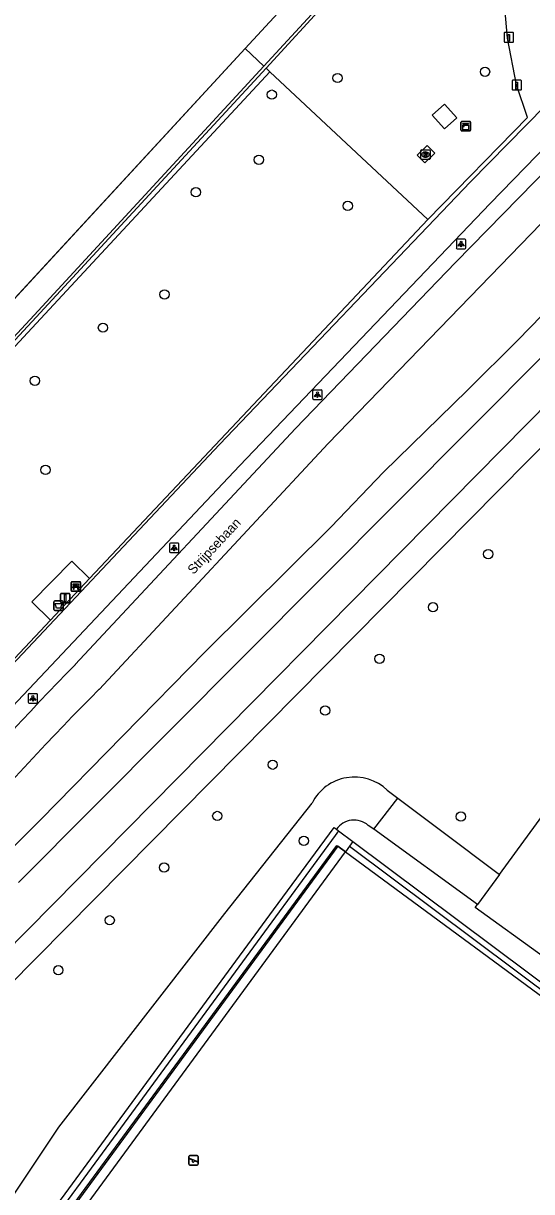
# Model space of a CAD drawing. Extents: x 155640 to 156810, y 382822 to 384046.
# Drawn here: x 156314.7 to 156368.2, y 383202.9 to 383326 of the extents above; entities that cross this region are included whole.
import ezdxf

# ---------------------------------------------------------------- set-up
doc = ezdxf.new("R2010")
doc.units = 0
for name, color, linetype in [('IMGEO_Afvalbak', 7, 'Continuous'), ('IMGEO_Bank', 7, 'Continuous'), ('IMGEO_Berm_groen', 7, 'Continuous'), ('IMGEO_Boom', 7, 'Continuous'), ('IMGEO_Fietspad_gesloten', 7, 'Continuous'), ('IMGEO_Groenvoorziening', 7, 'Continuous'), ('IMGEO_Haag', 7, 'Continuous'), ('IMGEO_Hek', 7, 'Continuous'), ('IMGEO_Kast', 7, 'Continuous'), ('IMGEO_Lichtpunt', 7, 'Continuous'), ('IMGEO_Openbare_ruimte_label', 7, 'Continuous'), ('IMGEO_Paal', 7, 'Continuous'), ('IMGEO_Pand', 7, 'Continuous'), ('IMGEO_Rioolput', 7, 'Continuous'), ('IMGEO_Speelvoorziening', 7, 'Continuous'), ('IMGEO_Verkeersbordpaal', 7, 'Continuous'), ('IMGEO_Voetpad_gesloten', 7, 'Continuous'), ('IMGEO_Voetpad_open', 7, 'Continuous'), ('IMGEO_Waterloop', 7, 'Continuous')]:
    doc.layers.add(name, color=color, linetype=linetype)

msp = doc.modelspace()

# ---------------------------------------------------------------- linework, layer by layer
at = {"layer": 'IMGEO_Afvalbak'}
for p, q in [((156317.87, 383264.25), (156317.87, 383265.05)), ((156317.87, 383265.05), (156317.87, 383264.25)), ((156317.97, 383265.15), (156318.76, 383265.15)), ((156318.76, 383265.15), (156317.97, 383265.15)), ((156318.86, 383265.05), (156318.86, 383264.25)), ((156318.86, 383264.25), (156318.86, 383265.05)), ((156318.76, 383264.15), (156317.97, 383264.15)), ((156317.97, 383264.15), (156318.76, 383264.15))]:
    msp.add_line(p, q, dxfattribs=at)
msp.add_lwpolyline([(156318.02, 383264.86), (156318.72, 383264.86), (156318.57, 383264.39), (156318.17, 383264.39), (156318.02, 383264.86)], dxfattribs=at)
for centre, start, end in [((156317.97, 383265.05), 90, 180), ((156317.97, 383265.05), 90, 180), ((156318.76, 383265.05), 0, 90), ((156318.76, 383265.05), 360, 90), ((156317.97, 383264.25), 180, 270), ((156317.97, 383264.25), 180, 270), ((156318.76, 383264.25), 270, 0), ((156318.76, 383264.25), 270, 0)]:
    msp.add_arc(centre, 0.1, start, end, dxfattribs=at)
at = {"layer": 'IMGEO_Bank'}
for p, q in [((156319.7, 383266.23), (156319.7, 383267.07)), ((156319.7, 383267.07), (156319.7, 383266.23)), ((156319.77, 383267.16), (156320.62, 383267.16)), ((156320.62, 383267.16), (156319.77, 383267.16)), ((156320.7, 383267.08), (156320.7, 383266.24)), ((156320.7, 383266.24), (156320.7, 383267.08)), ((156320.63, 383266.16), (156319.78, 383266.16)), ((156319.78, 383266.16), (156320.63, 383266.16)), ((156320.4, 383266.55), (156320, 383266.55)), ((156320.01, 383266.66), (156320.01, 383266.77)), ((156320.05, 383266.77), (156320.05, 383266.66)), ((156320.34, 383266.77), (156320.06, 383266.77)), ((156320.06, 383266.66), (156320.34, 383266.66)), ((156320.35, 383266.66), (156320.35, 383266.77)), ((156320.39, 383266.77), (156320.39, 383266.66))]:
    msp.add_line(p, q, dxfattribs=at)
for points in [[(156319.95, 383266.55), (156319.8, 383266.55), (156319.92, 383266.66), (156320, 383266.66)], [(156320, 383266.77), (156319.92, 383266.77), (156319.92, 383266.94), (156320.48, 383266.94), (156320.48, 383266.77), (156320.4, 383266.77)], [(156320, 383266.55), (156320, 383266.34), (156319.95, 383266.34), (156319.95, 383266.55)], [(156320.4, 383266.66), (156320.48, 383266.66), (156320.59, 383266.55), (156320.45, 383266.55)], [(156320.45, 383266.55), (156320.45, 383266.34), (156320.4, 383266.34), (156320.4, 383266.55)]]:
    msp.add_lwpolyline(points, dxfattribs=at)
for centre, radius, start, end in [((156319.78, 383267.08), 0.0779, 92.4484, 184.2845), ((156319.78, 383267.08), 0.0779, 92.4484, 184.2845), ((156320.62, 383267.08), 0.0779, 2.4484, 94.2845), ((156320.62, 383267.08), 0.0779, 2.4484, 94.2845), ((156319.78, 383266.24), 0.0779, 182.4484, 274.2845), ((156319.78, 383266.24), 0.0779, 182.4484, 274.2845), ((156319.95, 383266.55), 0.00671, 2.8957, 87.1043), ((156320, 383266.77), 0.00671, 2.8957, 87.1043), ((156320, 383266.66), 0.00671, 272.8957, 357.1043), ((156320, 383266.55), 0.00671, 92.8957, 177.1043), ((156320.06, 383266.77), 0.00671, 92.8957, 177.1043), ((156320.06, 383266.66), 0.00671, 182.8957, 267.1043), ((156320.34, 383266.77), 0.00671, 2.8957, 87.1043), ((156320.34, 383266.66), 0.00671, 272.8957, 357.1043), ((156320.4, 383266.77), 0.00671, 92.8957, 177.1043), ((156320.4, 383266.66), 0.00671, 182.8957, 267.1043), ((156320.4, 383266.55), 0.00671, 2.8957, 87.1043), ((156320.45, 383266.55), 0.00671, 92.8957, 177.1043), ((156320.62, 383266.24), 0.0779, 272.4484, 4.2845), ((156320.62, 383266.24), 0.0779, 272.4484, 4.2845)]:
    msp.add_arc(centre, radius, start, end, dxfattribs=at)
at = {"layer": 'IMGEO_Berm_groen'}
msp.add_lwpolyline([(156233.03, 383113.17), (156252.87, 383146.34), (156268.6, 383172.65), (156299.81, 383224.82), (156307.16, 383232.79), (156316.47, 383242.07), (156333.8, 383259.79), (156347.07, 383272.96), (156352.59, 383278.7), (156361.43, 383287.34), (156366.72, 383292.6), (156371.83, 383297.85), (156374.75, 383300.78), (156375.78, 383301.56), (156376.76, 383302.04), (156377.67, 383302.26), (156378.4, 383302.19), (156379.25, 383300.96), (156381.37, 383298.41), (156381.9, 383296.9), (156381.82, 383296.44)], dxfattribs=at)
at = {"layer": 'IMGEO_Boom'}
for centre in [(156363.28, 383320.89), (156347.75, 383320.23), (156340.83, 383318.48), (156339.47, 383311.62), (156332.84, 383308.2), (156348.83, 383306.76), (156329.53, 383297.43), (156323.05, 383293.93), (156315.88, 383288.34), (156317, 383278.95), (156363.62, 383270.08), (156357.8, 383264.48), (156352.17, 383259.05), (156346.45, 383253.59), (156340.92, 383247.89), (156335.09, 383242.49), (156360.74, 383242.43), (156344.2, 383239.87), (156329.49, 383237.06), (156323.76, 383231.5), (156318.35, 383226.24)]:
    msp.add_circle(centre, 0.489, dxfattribs=at)
at = {"layer": 'IMGEO_Fietspad_gesloten'}
for points in [[(156380.19, 383321.22), (156360.18, 383300.8), (156343.33, 383283.31), (156320.14, 383258.45)], [(156373.43, 383309.29), (156346.78, 383281.73), (156322.64, 383255.83)]]:
    msp.add_lwpolyline(points, dxfattribs=at)
for centre, radius, start, end in [((156587.61, 382998.36), 373.08, 135.8003, 142.4789), ((156555.25, 383025.41), 327.42, 135.271, 142.7864)]:
    msp.add_arc(centre, radius, start, end, dxfattribs=at)
at = {"layer": 'IMGEO_Groenvoorziening'}
for points in [[(156357.25, 383305.32), (156367.75, 383316.07), (156366.58, 383319.5), (156365.66, 383324.43), (156365.29, 383328.46), (156365.54, 383332.04), (156366.67, 383336.3), (156360.1, 383342.13), (156329.37, 383369.36), (156313.77, 383385.4), (156306.65, 383393.61), (156299.36, 383400.93)], [(156288.95, 383393.96), (156316.64, 383368.45), (156350.49, 383336.86), (156338.02, 383323.34)], [(156338.02, 383323.34), (156309.57, 383292.51)], [(156338.02, 383323.34), (156340, 383321.48)], [(156340.22, 383321.28), (156340.63, 383320.89)], [(156340.63, 383320.89), (156263.23, 383237.5), (156269.6, 383231.1), (156281.37, 383219.26), (156285.68, 383225.7), (156290.18, 383232.04), (156294.91, 383238.21), (156299.88, 383244.1), (156305.05, 383249.89), (156317.51, 383263.11)], [(156340.63, 383320.89), (156357.25, 383305.32)], [(156321.64, 383267.49), (156357.25, 383305.32)], [(156381.82, 383296.44), (156381.71, 383295.88), (156381.07, 383294.35), (156380.04, 383292.49), (156379.11, 383291.06), (156378.01, 383290.13), (156376.6, 383288.82), (156373.81, 383286.02), (156313.07, 383224.54), (156307.2, 383217.74), (156241.78, 383106.75)], [(156348.59, 383238.71), (156375.36, 383218.99), (156378.41, 383223.14), (156420.05, 383279.86), (156508.01, 383215.28), (156463.33, 383154.47)], [(156364.79, 383236.34), (156370.31, 383243.89), (156369.57, 383244.47), (156383.71, 383263.94), (156385.33, 383262.76), (156387.53, 383265.66), (156391.32, 383262.89), (156389.23, 383259.91), (156390.72, 383258.76), (156401.82, 383273.86)], [(156352.99, 383245.2), (156354.1, 383244.36)], [(156274.52, 383137.65), (156272.97, 383139.84), (156287.11, 383161.71), (156301.3, 383184.1), (156318.42, 383209.69), (156335.89, 383232.22), (156345.08, 383243.85)], [(156351.56, 383241.09), (156354.1, 383244.36)], [(156354.1, 383244.36), (156358.6, 383240.99), (156364.79, 383236.34)], [(156351.56, 383241.09), (156350.99, 383241.5)], [(156347.86, 383240.92), (156349.37, 383239.8)], [(156362.47, 383233.16), (156351.56, 383241.09)], [(156263.21, 383119.65), (156264.36, 383121.23), (156288.72, 383154.97), (156291.74, 383159.18), (156306.4, 383179.59), (156304.62, 383180.71), (156347.66, 383239.39), (156347.78, 383239.3)], [(156349.01, 383239.31), (156348.59, 383238.71)], [(156364.79, 383236.34), (156362.47, 383233.16)], [(156369.65, 383227.96), (156369.42, 383227.64), (156362.25, 383232.86), (156362.47, 383233.16)]]:
    msp.add_lwpolyline(points, dxfattribs=at)
for centre, radius, start, end in [((156349.53, 383241.59), 5, 46.2363, 153.0781), ((156349.49, 383239.78), 2.28, 48.9249, 144.7835)]:
    msp.add_arc(centre, radius, start, end, dxfattribs=at)
at = {"layer": 'IMGEO_Haag'}
for points in [[(156346.65, 383328.74), (156340, 383321.48)], [(156340.22, 383321.28), (156346.88, 383328.53), (156346.65, 383328.74)], [(156340, 383321.48), (156315.81, 383295.23), (156259.53, 383234.53), (156235.77, 383256.44), (156228.39, 383263.35)], [(156259.55, 383234.11), (156316.03, 383295.02), (156340.22, 383321.28)], [(156274.52, 383137.65), (156304.64, 383179.46), (156302.9, 383180.65), (156341.02, 383232.61), (156347.38, 383241.29), (156347.63, 383241.1)], [(156347.86, 383240.92), (156347.5, 383240.44), (156303.8, 383180.86), (156305.52, 383179.66), (156262.61, 383120.09)], [(156347.63, 383241.1), (156347.86, 383240.92)], [(156349.37, 383239.8), (156349.01, 383239.31)], [(156349.01, 383239.31), (156375.35, 383219.61), (156376.03, 383220.55)], [(156349.37, 383239.8), (156375.22, 383220.46), (156375.57, 383220.93)]]:
    msp.add_lwpolyline(points, dxfattribs=at)
at = {"layer": 'IMGEO_Hek'}
for points in [[(156284.23, 383388.92), (156288.95, 383393.96), (156316.64, 383368.45), (156350.49, 383336.86), (156338.02, 383323.34)], [(156338.02, 383323.34), (156309.48, 383292.4)], [(156340.63, 383320.89), (156263.23, 383237.5), (156269.6, 383231.1)], [(156357.25, 383305.32), (156340.63, 383320.89)], [(156281.37, 383219.26), (156285.68, 383225.7), (156290.18, 383232.04), (156294.91, 383238.21), (156299.88, 383244.1), (156305.05, 383249.89), (156317.51, 383263.11), (156321.64, 383267.49), (156357.25, 383305.32)], [(156291.74, 383159.18), (156306.4, 383179.59), (156304.62, 383180.71), (156347.66, 383239.39), (156347.78, 383239.3)], [(156348.59, 383238.71), (156347.78, 383239.3)], [(156348.59, 383238.71), (156375.36, 383218.99), (156378.41, 383223.14)]]:
    msp.add_lwpolyline(points, dxfattribs=at)
at = {"layer": 'IMGEO_Kast'}
for p, q in [((156360.75, 383314.73), (156360.75, 383315.57)), ((156360.75, 383315.57), (156360.75, 383314.73)), ((156360.83, 383315.66), (156361.67, 383315.66)), ((156361.67, 383315.66), (156360.83, 383315.66)), ((156361.75, 383315.58), (156361.75, 383314.74)), ((156361.75, 383314.74), (156361.75, 383315.58)), ((156361.68, 383314.66), (156360.84, 383314.66)), ((156360.84, 383314.66), (156361.68, 383314.66))]:
    msp.add_line(p, q, dxfattribs=at)
for points in [[(156360.95, 383315.45), (156361.55, 383315.45), (156361.55, 383315.36), (156360.95, 383315.36), (156360.95, 383315.45)], [(156360.95, 383315.27), (156361.55, 383315.27), (156361.55, 383314.78), (156360.95, 383314.78), (156360.95, 383315.27)]]:
    msp.add_lwpolyline(points, dxfattribs=at)
msp.add_circle((156361.03, 383315.12), 0.0377, dxfattribs=at)
for centre, start, end in [((156360.83, 383315.58), 92.4484, 184.2845), ((156360.83, 383315.58), 92.4484, 184.2845), ((156361.67, 383315.58), 2.4484, 94.2845), ((156361.67, 383315.58), 2.4484, 94.2845), ((156360.83, 383314.73), 182.4484, 274.2845), ((156360.83, 383314.73), 182.4484, 274.2845), ((156361.67, 383314.73), 272.4484, 4.2845), ((156361.67, 383314.73), 272.4484, 4.2845)]:
    msp.add_arc(centre, 0.0779, start, end, dxfattribs=at)
at = {"layer": 'IMGEO_Lichtpunt'}
for p, q in [((156360.26, 383303.15), (156360.26, 383302.34)), ((156360.26, 383303.15), (156360.26, 383302.34)), ((156361.16, 383303.24), (156360.35, 383303.24)), ((156361.16, 383303.24), (156360.35, 383303.24)), ((156361.26, 383302.34), (156361.26, 383303.15)), ((156361.26, 383302.34), (156361.26, 383303.15)), ((156360.35, 383302.25), (156361.16, 383302.25)), ((156360.35, 383302.25), (156361.16, 383302.25)), ((156345.13, 383287.27), (156345.13, 383286.46)), ((156345.13, 383287.27), (156345.13, 383286.46)), ((156346.03, 383287.36), (156345.23, 383287.36)), ((156346.03, 383287.36), (156345.23, 383287.36)), ((156346.13, 383286.46), (156346.13, 383287.27)), ((156346.13, 383286.46), (156346.13, 383287.27)), ((156345.23, 383286.37), (156346.03, 383286.37)), ((156345.23, 383286.37), (156346.03, 383286.37)), ((156330.06, 383271.14), (156330.06, 383270.33)), ((156330.06, 383271.14), (156330.06, 383270.33)), ((156330.96, 383271.23), (156330.15, 383271.23)), ((156330.96, 383271.23), (156330.15, 383271.23)), ((156331.05, 383270.33), (156331.05, 383271.14)), ((156331.05, 383270.33), (156331.05, 383271.14)), ((156330.15, 383270.23), (156330.96, 383270.23)), ((156330.15, 383270.23), (156330.96, 383270.23)), ((156315.17, 383255.28), (156315.17, 383254.47)), ((156315.17, 383255.28), (156315.17, 383254.47)), ((156316.07, 383255.37), (156315.27, 383255.37)), ((156316.07, 383255.37), (156315.27, 383255.37)), ((156316.17, 383254.47), (156316.17, 383255.28)), ((156316.17, 383254.47), (156316.17, 383255.28)), ((156315.27, 383254.38), (156316.07, 383254.38)), ((156315.27, 383254.38), (156316.07, 383254.38))]:
    msp.add_line(p, q, dxfattribs=at)
for points in [[(156360.63, 383302.81), (156360.67, 383302.78), (156360.48, 383302.52), (156360.45, 383302.55), (156360.63, 383302.81)], [(156360.73, 383302.76), (156360.78, 383302.76), (156360.78, 383302.44), (156360.73, 383302.44), (156360.73, 383302.76)], [(156360.84, 383302.78), (156360.88, 383302.81), (156361.07, 383302.55), (156361.03, 383302.52), (156360.84, 383302.78)], [(156345.51, 383286.93), (156345.54, 383286.9), (156345.36, 383286.64), (156345.32, 383286.67), (156345.51, 383286.93)], [(156345.61, 383286.88), (156345.65, 383286.88), (156345.65, 383286.56), (156345.61, 383286.56), (156345.61, 383286.88)], [(156345.72, 383286.9), (156345.76, 383286.93), (156345.94, 383286.67), (156345.9, 383286.64), (156345.72, 383286.9)], [(156330.43, 383270.8), (156330.47, 383270.77), (156330.28, 383270.51), (156330.24, 383270.54), (156330.43, 383270.8)], [(156330.53, 383270.75), (156330.58, 383270.75), (156330.58, 383270.43), (156330.53, 383270.43), (156330.53, 383270.75)], [(156330.64, 383270.77), (156330.68, 383270.8), (156330.87, 383270.54), (156330.83, 383270.51), (156330.64, 383270.77)], [(156315.55, 383254.94), (156315.58, 383254.91), (156315.4, 383254.65), (156315.36, 383254.68), (156315.55, 383254.94)], [(156315.65, 383254.89), (156315.7, 383254.89), (156315.7, 383254.57), (156315.65, 383254.57), (156315.65, 383254.89)], [(156315.76, 383254.91), (156315.8, 383254.94), (156315.98, 383254.68), (156315.94, 383254.65), (156315.76, 383254.91)]]:
    msp.add_lwpolyline(points, dxfattribs=at)
for centre in [(156360.76, 383302.95), (156345.63, 383287.07), (156330.56, 383270.93), (156315.67, 383255.08)]:
    msp.add_circle(centre, 0.0994, dxfattribs=at)
for centre, start, end in [((156360.35, 383303.15), 90, 180), ((156360.35, 383303.15), 90, 180), ((156361.16, 383303.15), 0, 90), ((156361.16, 383303.15), 0, 90), ((156360.35, 383302.34), 180, 270), ((156360.35, 383302.34), 180, 270), ((156361.16, 383302.34), 270, 0), ((156361.16, 383302.34), 270, 360), ((156345.23, 383287.27), 90, 180), ((156345.23, 383287.27), 90, 180), ((156346.03, 383287.27), 0, 90), ((156346.03, 383287.27), 0, 90), ((156345.23, 383286.46), 180, 270), ((156345.23, 383286.46), 180, 270), ((156346.03, 383286.46), 270, 0), ((156346.03, 383286.46), 270, 360), ((156330.15, 383271.14), 90, 180), ((156330.15, 383271.14), 90, 180), ((156330.96, 383271.14), 0, 90), ((156330.96, 383271.14), 0, 90), ((156330.15, 383270.33), 180, 270), ((156330.15, 383270.33), 180, 270), ((156330.96, 383270.33), 270, 0), ((156330.96, 383270.33), 270, 360), ((156315.27, 383255.28), 90, 180), ((156315.27, 383255.28), 90, 180), ((156316.07, 383255.28), 0, 90), ((156316.07, 383255.28), 0, 90), ((156315.27, 383254.47), 180, 270), ((156315.27, 383254.47), 180, 270), ((156316.07, 383254.47), 270, 0), ((156316.07, 383254.47), 270, 360)]:
    msp.add_arc(centre, 0.0946, start, end, dxfattribs=at)
at = {"layer": 'IMGEO_Paal'}
for p, q in [((156365.29, 383324.93), (156365.29, 383324.09)), ((156365.29, 383324.93), (156365.29, 383324.09)), ((156366.2, 383325.02), (156365.36, 383325.02)), ((156366.2, 383325.02), (156365.36, 383325.02)), ((156366.29, 383324.1), (156366.29, 383324.94)), ((156366.29, 383324.1), (156366.29, 383324.94)), ((156365.37, 383324.02), (156366.21, 383324.02)), ((156365.37, 383324.02), (156366.21, 383324.02)), ((156367.04, 383319.99), (156366.2, 383319.99)), ((156367.04, 383319.99), (156366.2, 383319.99)), ((156366.13, 383319.91), (156366.13, 383319.07)), ((156366.13, 383319.91), (156366.13, 383319.07)), ((156366.21, 383318.99), (156367.05, 383318.99)), ((156366.21, 383318.99), (156367.05, 383318.99)), ((156367.12, 383319.08), (156367.12, 383319.92)), ((156367.12, 383319.08), (156367.12, 383319.92))]:
    msp.add_line(p, q, dxfattribs=at)
for points in [[(156365.7, 383324.83), (156365.86, 383324.83), (156365.86, 383324.1), (156365.7, 383324.1), (156365.7, 383324.83)], [(156366.54, 383319.8), (156366.7, 383319.8), (156366.7, 383319.07), (156366.54, 383319.07), (156366.54, 383319.8)]]:
    msp.add_lwpolyline(points, dxfattribs=at)
for centre, start, end in [((156365.37, 383324.94), 92.4484, 184.2845), ((156365.37, 383324.94), 92.4484, 184.2845), ((156366.21, 383324.94), 2.4484, 94.2845), ((156366.21, 383324.94), 2.4484, 94.2845), ((156365.37, 383324.09), 182.4484, 274.2845), ((156365.37, 383324.09), 182.4484, 274.2845), ((156366.21, 383324.09), 272.4484, 4.2845), ((156366.21, 383324.09), 272.4484, 4.2845), ((156366.2, 383319.91), 92.4484, 184.2845), ((156366.2, 383319.91), 92.4484, 184.2845), ((156367.05, 383319.91), 2.4484, 94.2845), ((156367.05, 383319.91), 2.4484, 94.2845), ((156366.2, 383319.07), 182.4484, 274.2845), ((156366.2, 383319.07), 182.4484, 274.2845), ((156367.05, 383319.07), 272.4484, 4.2845), ((156367.05, 383319.07), 272.4484, 4.2845)]:
    msp.add_arc(centre, 0.0779, start, end, dxfattribs=at)
at = {"layer": 'IMGEO_Pand'}
msp.add_lwpolyline([(156359.03, 383317.48), (156360.32, 383316.03), (156359, 383314.86), (156357.72, 383316.31), (156359.03, 383317.48)], dxfattribs=at)
at = {"layer": 'IMGEO_Rioolput'}
for p, q in [((156356.51, 383311.73), (156356.51, 383312.59)), ((156356.58, 383312.66), (156357.44, 383312.66)), ((156357.51, 383312.59), (156357.51, 383311.73)), ((156357.44, 383311.66), (156356.58, 383311.66)), ((156357, 383312.44), (156357.02, 383312.44)), ((156357.02, 383311.88), (156357, 383311.88))]:
    msp.add_line(p, q, dxfattribs=at)
for points in [[(156356.51, 383311.73), (156356.51, 383312.59)], [(156356.58, 383312.66), (156357.44, 383312.66)], [(156357.51, 383312.59), (156357.51, 383311.73)], [(156357.44, 383311.66), (156356.58, 383311.66)], [(156357.1, 383312.36), (156356.85, 383312.36), (156356.85, 383311.96)], [(156356.85, 383311.96), (156356.97, 383311.96), (156356.97, 383312.12), (156356.98, 383312.12)], [(156357.03, 383312.28), (156356.97, 383312.28), (156356.97, 383312.2)], [(156356.97, 383312.2), (156357.02, 383312.2)], [(156357.03, 383312.09), (156357.1, 383311.96), (156357.24, 383311.96), (156357.17, 383312.09)]]:
    msp.add_lwpolyline(points, dxfattribs=at)
for centre, radius, start, end in [((156356.59, 383312.59), 0.0765, 91.552, 178.448), ((156356.59, 383312.59), 0.0765, 91.552, 178.448), ((156357.43, 383312.59), 0.0765, 1.552, 88.448), ((156357.43, 383312.59), 0.0765, 1.552, 88.448), ((156356.59, 383311.74), 0.0765, 181.552, 268.448), ((156356.59, 383311.74), 0.0765, 181.552, 268.448), ((156356.98, 383312.07), 0.0533, 26.0293, 88.6989), ((156357.01, 383312.39), 0.19, 274.7715, 282.9687), ((156357.03, 383312.18), 0.0964, 77.0061, 93.1865), ((156357.05, 383312.24), 0.0378, 276.6634, 79.6772), ((156357.1, 383312.25), 0.109, 350.3612, 89.416), ((156357.1, 383312.25), 0.112, 277.5842, 350.9817), ((156357.08, 383312.03), 0.108, 29.5134, 73.7905), ((156357.43, 383311.74), 0.0765, 271.552, 358.448), ((156357.43, 383311.74), 0.0765, 271.552, 358.448)]:
    msp.add_arc(centre, radius, start, end, dxfattribs=at)
for centre, major_axis, ratio, start_param, end_param in [((156357, 383312.16), (-0.387, 0.002), 0.722429, 4.712389, 7.853982), ((156357.02, 383312.16), (-0.39, 0.002), 0.717154, 1.570796, 4.712389)]:
    msp.add_ellipse(centre, major_axis=major_axis, ratio=ratio, start_param=start_param, end_param=end_param, dxfattribs=at)
at = {"layer": 'IMGEO_Speelvoorziening'}
for p, q in [((156332.09, 383205.81), (156332.09, 383206.61)), ((156332.09, 383206.61), (156332.09, 383205.81)), ((156332.47, 383206.24), (156332.13, 383206.37)), ((156332.16, 383206.43), (156333.03, 383206.08)), ((156332.19, 383206.71), (156332.98, 383206.71)), ((156332.98, 383206.71), (156332.19, 383206.71)), ((156332.98, 383205.71), (156332.19, 383205.71)), ((156332.19, 383205.71), (156332.98, 383205.71)), ((156333.01, 383206.02), (156332.67, 383206.16)), ((156333.08, 383206.61), (156333.08, 383205.81)), ((156333.08, 383205.81), (156333.08, 383206.61))]:
    msp.add_line(p, q, dxfattribs=at)
for centre, radius, start, end in [((156332.19, 383206.61), 0.1, 90, 180), ((156332.19, 383206.61), 0.1, 90, 180), ((156332.19, 383205.81), 0.1, 180, 270), ((156332.19, 383205.81), 0.1, 180, 270), ((156332.15, 383206.4), 0.0327, 68.078, 248.078), ((156332.55, 383206.14), 0.12, 130.9928, 5.1632), ((156332.98, 383206.61), 0.1, 0, 90), ((156332.98, 383206.61), 0.1, 360, 90), ((156332.98, 383205.81), 0.1, 270, 0), ((156332.98, 383205.81), 0.1, 270, 0), ((156333.02, 383206.05), 0.0327, 248.078, 68.078)]:
    msp.add_arc(centre, radius, start, end, dxfattribs=at)
at = {"layer": 'IMGEO_Verkeersbordpaal'}
for p, q in [((156318.58, 383265.04), (156318.58, 383265.84)), ((156318.58, 383265.84), (156318.58, 383265.04)), ((156318.68, 383265.94), (156319.47, 383265.94)), ((156319.47, 383265.94), (156318.68, 383265.94)), ((156319.57, 383265.84), (156319.57, 383265.04)), ((156319.57, 383265.04), (156319.57, 383265.84)), ((156319.47, 383264.94), (156318.68, 383264.94)), ((156318.68, 383264.94), (156319.47, 383264.94))]:
    msp.add_line(p, q, dxfattribs=at)
msp.add_lwpolyline([(156319, 383265.81), (156319.15, 383265.81), (156319.15, 383265.06), (156319, 383265.06), (156319, 383265.81)], dxfattribs=at)
for centre, start, end in [((156318.68, 383265.84), 90, 180), ((156318.68, 383265.84), 90, 180), ((156319.47, 383265.84), 0, 90), ((156319.47, 383265.84), 360, 90), ((156318.68, 383265.04), 180, 270), ((156318.68, 383265.04), 180, 270), ((156319.47, 383265.04), 270, 0), ((156319.47, 383265.04), 270, 0)]:
    msp.add_arc(centre, 0.1, start, end, dxfattribs=at)
at = {"layer": 'IMGEO_Voetpad_gesloten'}
for points in [[(156380.5, 383328.41), (156380.01, 383327.91), (156379.48, 383327.36), (156361.74, 383309.31), (156335.32, 383281.62), (156308.93, 383253.61)], [(156381.89, 383325.6), (156381.35, 383325.04), (156380.96, 383324.64), (156363.82, 383307), (156337.44, 383279.37), (156311.15, 383251.52)], [(156357.2, 383313.13), (156358, 383312.31), (156356.93, 383311.28), (156356.13, 383312.1), (156357.2, 383313.13)], [(156317.51, 383263.11), (156315.56, 383265.05), (156319.76, 383269.34), (156321.64, 383267.49)], [(156317.51, 383263.11), (156321.64, 383267.49)]]:
    msp.add_lwpolyline(points, dxfattribs=at)
at = {"layer": 'IMGEO_Voetpad_open'}
for points in [[(156347.78, 383239.3), (156304.83, 383180.74), (156306.54, 383179.51), (156291.86, 383159.1), (156267.49, 383125.26), (156264.51, 383121.14), (156263.35, 383119.54)], [(156347.78, 383239.3), (156348.59, 383238.71)], [(156351.16, 383056.69), (156339.34, 383065.33), (156331.51, 383071.05), (156264.73, 383119.75), (156268.38, 383124.75), (156289.66, 383154.32), (156307.95, 383179.75), (156306.22, 383180.96), (156348.59, 383238.71)]]:
    msp.add_lwpolyline(points, dxfattribs=at)
at = {"layer": 'IMGEO_Waterloop'}
msp.add_lwpolyline([(156309.84, 383225.15), (156375.53, 383291.73), (156379.35, 383298.18), (156377.72, 383299.34), (156314.17, 383235.48)], dxfattribs=at)

# ---------------------------------------------------------------- texts
at = {"layer": 'IMGEO_Openbare_ruimte_label'}
msp.add_text('Strijpsebaan', height=1, rotation=46.9861, dxfattribs=at).set_placement((156332.58, 383267.87))

doc.saveas('drawing.dxf')
